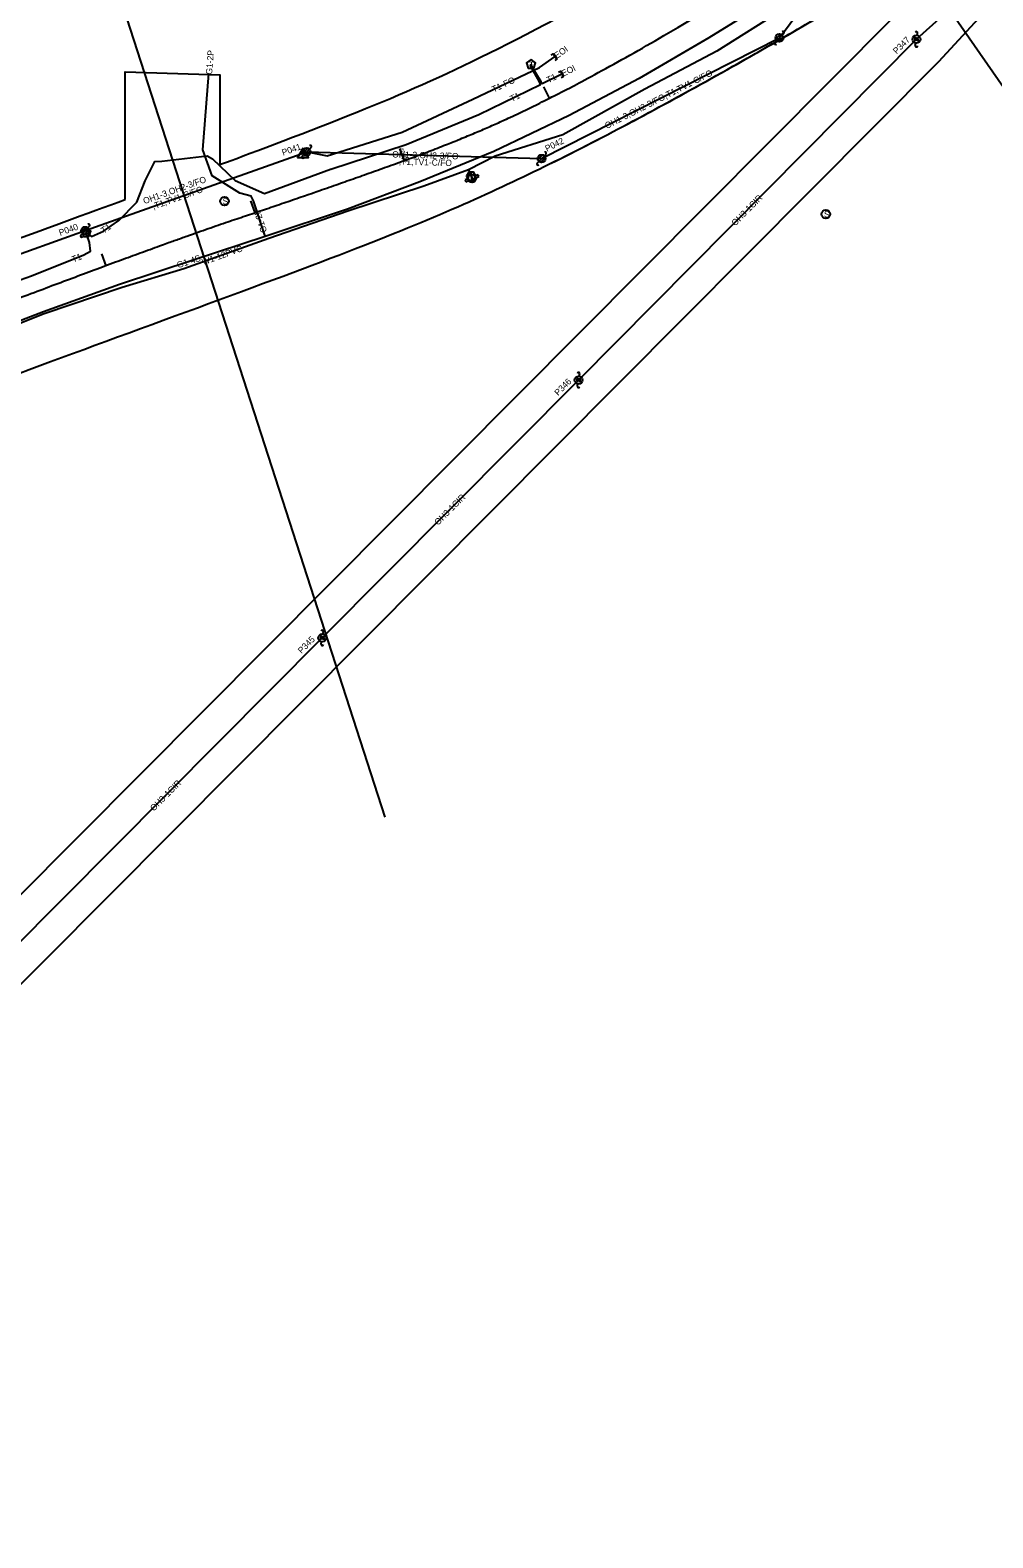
# Model space of a CAD drawing. Extents: x 1991878 to 2008544, y 770238 to 1141211.
# Drawn here: x 2006187 to 2006796, y 1139605 to 1140559 of the extents above; entities that cross this region are included whole.
import ezdxf

# ---------------------------------------------------------------- set-up
doc = ezdxf.new("R2010")
doc.units = 0
for name, color, linetype in [('RD_EX_SU_Gas', 7, 'Continuous'), ('RD_EX_SU_H2O', 7, 'Continuous'), ('RD_EX_SU_Misc', 7, 'Continuous'), ('RD_EX_SU_Ovhd', 7, 'Continuous'), ('RD_EX_SU_Pole', 7, 'Continuous'), ('RD_EX_SU_Sewer', 7, 'Continuous'), ('RD_EX_SU_SwpLmt', 7, 'Continuous'), ('RD_EX_SU_Telecom', 7, 'Continuous'), ('RD_EX_SU_TX_Gas', 7, 'Continuous'), ('RD_EX_SU_TX_H2O', 7, 'Continuous'), ('RD_EX_SU_TX_Ovhd', 7, 'Continuous'), ('RD_EX_SU_TX_Pole', 7, 'Continuous'), ('RD_EX_SU_TX_Telecom', 7, 'Continuous'), ('RD_HC_Cl', 7, 'Continuous')]:
    doc.layers.add(name, color=color, linetype=linetype)

msp = doc.modelspace()

# ---------------------------------------------------------------- linework, layer by layer
at = {"layer": 'RD_EX_SU_Gas'}
for points in [[(2006659, 1140580.57), (2006616.24, 1140554.03), (2006572.17, 1140528.34), (2006527.84, 1140504.87), (2006480.11, 1140482.2), (2006433.28, 1140463.04), (2006387.65, 1140445.69), (2006335.52, 1140428.39), (2006290.66, 1140413.7), (2006243.38, 1140398.08), (2006195.4, 1140380.79), (2006149.48, 1140363.23), (2006103.48, 1140345.61), (2006057.3, 1140326.02), (2006013.07, 1140306.27), (2005973.69, 1140284.77), (2005927.56, 1140258.36), (2005885.79, 1140232.42), (2005844.4, 1140205.05), (2005803.2, 1140176.39), (2005763.13, 1140146.95)], [(2006335.69, 1140428.44), (2006335.4, 1140429.31), (2006328.15, 1140450.82), (2006326.76, 1140453.87), (2006319.57, 1140455.82), (2006301.92, 1140466.72), (2006296.15, 1140483.27), (2006299.86, 1140531.39)]]:
    msp.add_lwpolyline(points, dxfattribs=at)
at = {"layer": 'RD_EX_SU_H2O'}
for p, q in [((2006465.46, 1140469.12), (2006464.29, 1140468.65)), ((2006464.29, 1140468.65), (2006464.9, 1140467.16)), ((2006466.08, 1140467.61), (2006465.46, 1140469.12)), ((2006470.2, 1140467.46), (2006468.32, 1140466.69)), ((2006470.68, 1140466.29), (2006470.2, 1140467.46)), ((2006463.86, 1140464.86), (2006462.04, 1140464.12)), ((2006462.04, 1140464.12), (2006462.52, 1140462.95)), ((2006462.52, 1140462.95), (2006464.29, 1140463.68)), ((2006468.85, 1140465.54), (2006470.68, 1140466.29))]:
    msp.add_line(p, q, dxfattribs=at)
for points in [[(2006662.73, 1140571.78), (2006621.15, 1140545.52), (2006575.62, 1140521.49), (2006523.9, 1140492.67), (2006480.95, 1140479.12), (2006464.19, 1140470.57), (2006435.9, 1140460.17), (2006387.84, 1140444.29), (2006337.78, 1140427.16), (2006284, 1140408), (2006245, 1140396.17), (2006195.82, 1140379.38), (2006150.58, 1140361.49), (2006104.78, 1140343.73), (2006057.98, 1140322.59), (2006016.46, 1140300.24), (2005977.38, 1140278.75), (2005932.66, 1140252.06), (2005891.14, 1140226.62), (2005848.84, 1140199.57), (2005807.57, 1140171.15), (2005766.02, 1140142.13)], [(2006464.23, 1140470.58), (2006464.6, 1140469.58), (2006466.07, 1140465.6), (2006466.36, 1140465.11)]]:
    msp.add_lwpolyline(points, dxfattribs=at)
msp.add_lwpolyline([(2006468.67, 1140466.45), (2006467.23, 1140468.95), (2006464.34, 1140468.95), (2006462.9, 1140466.45), (2006464.34, 1140463.95), (2006467.23, 1140463.95)], close=True, dxfattribs=at)
for radius in [2.52, 0.315]:
    msp.add_circle((2006466.36, 1140465.11), radius, dxfattribs=at)
for start, end in [(96.4954, 125.46263), (9.93486, 38.91118), (185.58857, 214.56489)]:
    msp.add_arc((2006466.36, 1140465.11), 2.52, start, end, dxfattribs=at)
at = {"layer": 'RD_EX_SU_Misc'}
msp.add_lwpolyline([(2006359.54, 1140484.26), (2006356.07, 1140478.26), (2006363, 1140478.26)], close=True, dxfattribs=at)
at = {"layer": 'RD_EX_SU_Ovhd'}
for p, q in [((2006660.79, 1140553.98), (2006771.97, 1140703.38)), ((2006870.01, 1140663.43), (2006747.45, 1140553.1)), ((2006510.35, 1140477.61), (2006660.79, 1140553.98)), ((2006747.45, 1140553.1), (2006533.75, 1140337.58)), ((2006221.67, 1140432.07), (2006361.78, 1140481.92)), ((2006361.78, 1140481.92), (2006510.35, 1140477.61)), ((2006082.85, 1140382.57), (2006221.67, 1140432.07)), ((2006533.75, 1140337.58), (2006371.59, 1140174.52)), ((2006371.59, 1140174.52), (2006174.14, 1139975.99))]:
    msp.add_line(p, q, dxfattribs=at)
at = {"layer": 'RD_EX_SU_Pole'}
for p, q in [((2006657.96, 1140551.15), (2006659.02, 1140552.21)), ((2006658.37, 1140553.33), (2006661.43, 1140556.39)), ((2006659.02, 1140552.21), (2006662.55, 1140555.75)), ((2006660.14, 1140551.56), (2006663.2, 1140554.63)), ((2006662.55, 1140555.75), (2006663.61, 1140556.81)), ((2006747.9, 1140555.56), (2006748.16, 1140557.04)), ((2006746.73, 1140549.17), (2006747, 1140550.64)), ((2006358.96, 1140479.09), (2006360.02, 1140480.15)), ((2006359.37, 1140481.27), (2006362.43, 1140484.33)), ((2006360.02, 1140480.15), (2006363.55, 1140483.69)), ((2006361.14, 1140479.5), (2006364.2, 1140482.57)), ((2006363.55, 1140483.69), (2006364.61, 1140484.75)), ((2006507.93, 1140476.97), (2006510.99, 1140480.03)), ((2006508.58, 1140475.84), (2006512.11, 1140479.38)), ((2006509.7, 1140475.2), (2006512.76, 1140478.26)), ((2006512.11, 1140479.38), (2006513.17, 1140480.44)), ((2006507.52, 1140474.78), (2006508.58, 1140475.84)), ((2006218.84, 1140429.24), (2006219.9, 1140430.3)), ((2006219.25, 1140431.43), (2006222.31, 1140434.49)), ((2006219.9, 1140430.3), (2006223.43, 1140433.84)), ((2006221.02, 1140429.66), (2006224.08, 1140432.72)), ((2006223.43, 1140433.84), (2006224.49, 1140434.9)), ((2006533.04, 1140333.65), (2006533.31, 1140335.12)), ((2006534.2, 1140340.04), (2006534.47, 1140341.52)), ((2006370.88, 1140170.58), (2006371.15, 1140172.06)), ((2006372.04, 1140176.97), (2006372.31, 1140178.45))]:
    msp.add_line(p, q, dxfattribs=at)
for points in [[(2006745.98, 1140554.53), (2006747.81, 1140553.34), (2006746.15, 1140553.17), (2006749.22, 1140552.04), (2006749.22, 1140552.04), (2006747.04, 1140553.08), (2006748.63, 1140553.2)], [(2006532.28, 1140339.01), (2006534.11, 1140337.82), (2006532.46, 1140337.65), (2006535.53, 1140336.51), (2006535.53, 1140336.51), (2006533.34, 1140337.56), (2006534.94, 1140337.68)], [(2006370.12, 1140175.94), (2006371.95, 1140174.76), (2006370.3, 1140174.59), (2006373.37, 1140173.45), (2006373.37, 1140173.45), (2006371.18, 1140174.49), (2006372.78, 1140174.62)]]:
    msp.add_lwpolyline(points, close=True, dxfattribs=at)
for centre in [(2006660.79, 1140553.98), (2006747.45, 1140553.1), (2006361.78, 1140481.92), (2006510.35, 1140477.61), (2006221.67, 1140432.07), (2006533.75, 1140337.58), (2006371.59, 1140174.51)]:
    msp.add_circle(centre, 2.5, dxfattribs=at)
for centre, start, end in [((2006663.08, 1140557.34), 315.01158, 135.01158), ((2006747.43, 1140557.17), 349.68899, 169.68899), ((2006658.49, 1140550.62), 135.01158, 315.01158), ((2006747.47, 1140549.03), 169.68899, 349.68899), ((2006364.08, 1140485.28), 315.01158, 135.01158), ((2006359.49, 1140478.56), 135.01158, 315.01158), ((2006512.64, 1140480.97), 315.01158, 135.01158), ((2006508.05, 1140474.25), 135.01158, 315.01158), ((2006219.37, 1140428.71), 135.01158, 315.01158), ((2006223.96, 1140435.43), 315.01158, 135.01158), ((2006533.73, 1140341.65), 349.68899, 169.68899), ((2006533.77, 1140333.51), 169.68899, 349.68899), ((2006371.57, 1140178.58), 349.68899, 169.68899), ((2006371.61, 1140170.45), 169.68899, 349.68899)]:
    msp.add_arc(centre, 0.75, start, end, dxfattribs=at)
at = {"layer": 'RD_EX_SU_Sewer'}
for centre in [(2006309.78, 1140450.68), (2006690.18, 1140442.43)]:
    msp.add_circle(centre, 2.75, dxfattribs=at)
at = {"layer": 'RD_EX_SU_SwpLmt'}
for points in [[(2005780.53, 1139609.9), (2006733.27, 1140567.21), (2006823.57, 1140659.06)], [(2005832.44, 1139605.35), (2006761.62, 1140538.99), (2006847.85, 1140632.58)], [(2006247.03, 1140451.84), (2006246.96, 1140532.47), (2006306.94, 1140530.67), (2006306.82, 1140473.81)]]:
    msp.add_lwpolyline(points, dxfattribs=at)
for points in [[(2006306.82, 1140473.81), (2006314.46, 1140476.64), (2006388.82, 1140504.33), (2006461.56, 1140535.38), (2006562.87, 1140588.57), (2006665.02, 1140647.19), (2006717.93, 1140680.37), (2006741.2, 1140697.07)], [(2005347.6, 1139821.95), (2005413.49, 1139866.73), (2005588.16, 1139984.08), (2005817.83, 1140151.69), (2006031.43, 1140278.81), (2006110.28, 1140318.03), (2006387.29, 1140416.7), (2006495.91, 1140463.06), (2006601.39, 1140518.44), (2006718.46, 1140585.62), (2006783.57, 1140627.26), (2006823.57, 1140659.06)], [(2005347.6, 1139821.95), (2005413.49, 1139866.73), (2005588.16, 1139984.08), (2005817.83, 1140151.69), (2006031.43, 1140278.81), (2006110.28, 1140318.03), (2006387.29, 1140416.7), (2006495.91, 1140463.06), (2006601.39, 1140518.44), (2006706.19, 1140578.58), (2006762.55, 1140613.92), (2006787.85, 1140632.08)], [(2005307.04, 1139891.13), (2005371.11, 1139934.66), (2005544.09, 1140050.96), (2005773.7, 1140218.52), (2005993.11, 1140349.1), (2006068.08, 1140386.39), (2006199.13, 1140434.31), (2006247.03, 1140451.84)]]:
    msp.add_open_spline(points, degree=3, dxfattribs=at)
at = {"layer": 'RD_EX_SU_Telecom'}
for points in [[(2006516.52, 1140542.99), (2006517.74, 1140543.86), (2006520.05, 1140540.59), (2006518.82, 1140539.72)], [(2006222.32, 1140430.74), (2006223.04, 1140430.25), (2006225.56, 1140428.26), (2006233.21, 1140431.84), (2006242.92, 1140438.49), (2006254.27, 1140450.02), (2006259.66, 1140463.67), (2006265.79, 1140475.77), (2006270.23, 1140476.08), (2006298.91, 1140479.3), (2006302.12, 1140477.49), (2006316.45, 1140463.8), (2006335.13, 1140455.61), (2006376.91, 1140471.04), (2006376.98, 1140471.04), (2006424.75, 1140486.65), (2006470.7, 1140505.5), (2006509.65, 1140524.45), (2006509, 1140526.2), (2006503.37, 1140536.27), (2006503.67, 1140537.33)], [(2006361.78, 1140481.92), (2006363.17, 1140481.61), (2006374.71, 1140479.34), (2006422.17, 1140494.32), (2006466.78, 1140515.29), (2006509.14, 1140535.34), (2006518.89, 1140542.22)], [(2006503.67, 1140537.33), (2006503.97, 1140536.1), (2006509.94, 1140526.4), (2006510.74, 1140525.04), (2006523.21, 1140531.2)], [(2006520.98, 1140532.33), (2006522.33, 1140533), (2006524.1, 1140529.41), (2006522.75, 1140528.75)], [(2005782.4, 1140210.68), (2005783.36, 1140209.78), (2005787.76, 1140202.94), (2005791.09, 1140198.01), (2005830.75, 1140225.72), (2005872.56, 1140254.44), (2005914.21, 1140280.3), (2005958.19, 1140305.05), (2005994.94, 1140324.79), (2006000.07, 1140334.17), (2006004.81, 1140335.92), (2006011.67, 1140336.58), (2006023.53, 1140337.8), (2006047.93, 1140349.44), (2006094.26, 1140368.64), (2006140.88, 1140386.98), (2006187.64, 1140403.41), (2006220.74, 1140416.68), (2006225.13, 1140419), (2006224.39, 1140424.64), (2006222.64, 1140429.44), (2006222.32, 1140430.74)]]:
    msp.add_lwpolyline(points, dxfattribs=at)
for points in [[(2006503.67, 1140540.33), (2006500.82, 1140538.26), (2006501.91, 1140534.9), (2006505.44, 1140534.9), (2006506.53, 1140538.26)], [(2006222.32, 1140433.74), (2006219.47, 1140431.66), (2006220.56, 1140428.31), (2006224.08, 1140428.31), (2006225.17, 1140431.66)]]:
    msp.add_lwpolyline(points, close=True, dxfattribs=at)
at = {"layer": 'RD_HC_Cl'}
for p, q in [((2006527.45, 1140919.17), (2006942.87, 1140320.65)), ((2006187.2, 1140754.29), (2006411.29, 1140061.06)), ((2006511.51, 1140523.04), (2006515.09, 1140515.89)), ((2006420.41, 1140484.08), (2006423.2, 1140476.58)), ((2006326.27, 1140450.93), (2006328.88, 1140443.37)), ((2006231.91, 1140417.3), (2006234.68, 1140409.79))]:
    msp.add_line(p, q, dxfattribs=at)
msp.add_open_spline([(2005275.25, 1139802.58), (2005417.33, 1139911.24), (2005548.93, 1140008.55), (2005664.1, 1140090.03), (2005747, 1140153.49), (2005819.82, 1140205.85), (2005880.88, 1140246.35), (2005986.62, 1140308.11), (2006024.68, 1140326.82), (2006100.51, 1140359.48), (2006273.91, 1140424.96), (2006364.15, 1140455.15), (2006461.52, 1140489.97), (2006524.81, 1140519.99), (2006584.45, 1140553.16), (2006699.96, 1140622.09), (2006754.11, 1140664.4), (2006830.67, 1140723.8), (2007317.85, 1141134.95)], degree=2, dxfattribs=at)

# ---------------------------------------------------------------- texts
at = {"layer": 'RD_EX_SU_H2O'}
msp.add_text('V', height=3.75, dxfattribs=at).set_placement((2006464.58, 1140464.57))
at = {"layer": 'RD_EX_SU_Misc'}
msp.add_text('U', height=2.4, dxfattribs=at).set_placement((2006358.78, 1140479.06))
at = {"layer": 'RD_EX_SU_Sewer'}
for p in [(2006308.57, 1140448.72), (2006688.97, 1140440.47)]:
    msp.add_text('S', height=3.93, dxfattribs=at).set_placement(p)
at = {"layer": 'RD_EX_SU_Telecom'}
for rotation, p in [(35.19015, (2006520.04, 1140540.58)), (26.28921, (2006524.09, 1140529.41))]:
    msp.add_text('EOI', height=4, rotation=rotation, dxfattribs=at).set_placement(p)
for p in [(2006502.44, 1140535.1), (2006221.09, 1140428.51)]:
    msp.add_text('T', height=3.75, dxfattribs=at).set_placement(p)
at = {"layer": 'RD_EX_SU_TX_Gas'}
for s, rotation, p in [('G1-2P', 85.58429, (2006301.94, 1140530.67)), ('G1-2P', 108.63139, (2006336.78, 1140431.54)), ('G1-4S', 18.12933, (2006280.44, 1140408.27))]:
    msp.add_text(s, height=4, rotation=rotation, dxfattribs=at).set_placement(p)
at = {"layer": 'RD_EX_SU_TX_H2O'}
msp.add_text('W1-12PVC', height=4, rotation=19.60885, dxfattribs=at).set_placement((2006296.4, 1140410.19))
at = {"layer": 'RD_EX_SU_TX_Ovhd'}
for s, rotation, p in [('OH1-3,OH2-3/FO,T1,TV1-C/FO', 26.91331, (2006551.61, 1140496.32)), ('OH1-3,OH2-3/FO', 358.3398, (2006415.85, 1140478.35)), (',T1,TV1-C/FO', 358.3398, (2006420.01, 1140473.83)), ('OH1-3,OH2-3/FO', 19.58292, (2006259.14, 1140448.81)), (',T1,TV1-C/FO', 19.58292, (2006264.93, 1140445.34)), ('OH3-1CIR', 45.24358, (2006632.84, 1140434.68)), ('OH3-1CIR', 45.1597, (2006444.9, 1140245.4)), ('OH3-1CIR', 45.15481, (2006265.09, 1140064.6))]:
    msp.add_text(s, height=4, rotation=rotation, dxfattribs=at).set_placement(p)
at = {"layer": 'RD_EX_SU_TX_Pole'}
for s, rotation, p in [('P347', 45.24358, (2006735.01, 1140543.46)), ('P041', 19.58292, (2006346.88, 1140479.4)), ('P042', 26.91331, (2006513.8, 1140481.88)), ('P040', 19.62616, (2006205.87, 1140428.69)), ('P346', 45.1597, (2006520.83, 1140327.38)), ('P345', 45.15481, (2006358.56, 1140164.29))]:
    msp.add_text(s, height=4, rotation=rotation, dxfattribs=at).set_placement(p)
at = {"layer": 'RD_EX_SU_TX_Telecom'}
for s, rotation, p in [('T1-FO', 25.33362, (2006480.05, 1140519.34)), ('T1', 26.28921, (2006514.7, 1140525.25)), ('T1', 25.93845, (2006491.55, 1140513.39)), ('T1', 34.42702, (2006233.34, 1140429.99)), ('T1', 21.85196, (2006214.15, 1140411.86))]:
    msp.add_text(s, height=4, rotation=rotation, dxfattribs=at).set_placement(p)
at = {"layer": 'RD_HC_Cl'}
msp.add_text('40+00', height=2.5, rotation=290.30128, dxfattribs=at).set_placement((2006420.45, 1140484.02))

doc.saveas('drawing.dxf')
